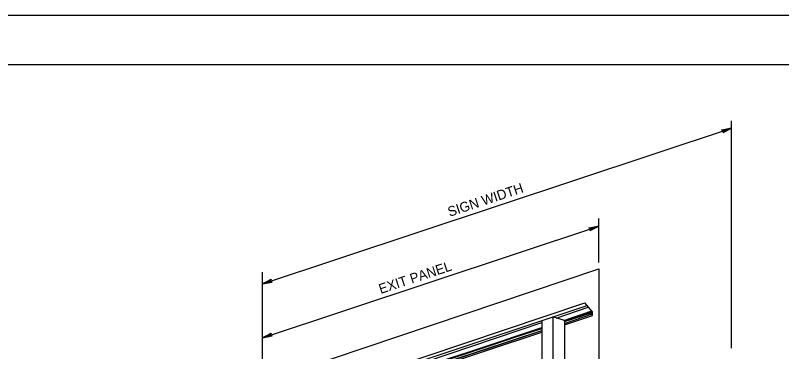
# Model space of a CAD drawing. Extents: x 650495 to 651400, y 297864 to 299646.
# Drawn here: x 650729.8 to 650964.3, y 299542.7 to 299645.6 of the extents above; entities that cross this region are included whole.
import ezdxf

# ---------------------------------------------------------------- set-up
doc = ezdxf.new("R2010")
doc.units = 0
for name, color, linetype in [('1', 7, 'Continuous'), ('2', 7, 'Continuous'), ('3', 7, 'Continuous'), ('PLT-BNDY', 7, 'Continuous')]:
    doc.layers.add(name, color=color, linetype=linetype)

# ---------------------------------------------------------------- blocks, each defined once
blk = doc.blocks.new('RARROW')
at = {"layer": '3'}
blk.add_lwpolyline([(-2.2695, 0.285), (-2.184875, 0.12075), (0, 0), (-2.2695, 0.285), (-2.38575, 0.384625), (0, 0), (-2.183125, -0.108), (-2.262875, -0.2705), (0, 0), (-2.38575, -0.379125), (-2.262875, -0.2705)], dxfattribs=at)

msp = doc.modelspace()

# ---------------------------------------------------------------- linework, layer by layer
at = {"layer": '1'}
msp.add_line((650535.31, 299630.63), (651321.31, 299630.63), dxfattribs=at)
at = {"layer": '2'}
for p, q in [((650948.9, 299543.77), (650948.9, 299613.37)), ((650805.4, 299563.47), (650948.9, 299611.07)), ((650908.3, 299569.97), (650908.3, 299583.47)), ((650805.4, 299546.97), (650908.3, 299581.07)), ((650908.3, 299581.07), (650908.3, 299581.07)), ((650805.4, 299533.47), (650908.3, 299568.07)), ((650805.4, 299535.47), (650805.4, 299567.07)), ((650908.3, 299568.07), (650908.3, 299528.47)), ((650809.3, 299525.87), (650904, 299557.67)), ((650906.4, 299554.87), (650904, 299557.67)), ((650904.7, 299556.77), (650832.8, 299532.87)), ((650895.3, 299552.97), (650905.1, 299556.37)), ((650897.6, 299552.27), (650906.2, 299555.17)), ((650897.8, 299552.17), (650906.4, 299554.87)), ((650897.8, 299551.97), (650906.4, 299554.67)), ((650906.4, 299553.77), (650906.4, 299554.97)), ((650890.9, 299552.27), (650890.9, 299482.47)), ((650894.3, 299553.37), (650894.3, 299483.87)), ((650897.8, 299552.27), (650894.3, 299553.37)), ((650897.8, 299551.37), (650906.4, 299554.27)), ((650897.8, 299550.97), (650906.4, 299553.77)), ((650897.8, 299552.27), (650897.8, 299482.67)), ((650832.8, 299532.07), (650890.9, 299551.67)), ((650834.4, 299531.27), (650890.9, 299550.07)), ((650834.7, 299531.17), (650890.9, 299549.87)), ((650833.9, 299531.57), (650890.9, 299549.77)), ((650837.1, 299531.57), (650890.9, 299549.17)), ((650837.1, 299531.37), (650891, 299549.17)), ((650837.1, 299530.97), (650890.9, 299548.67))]:
    msp.add_line(p, q, dxfattribs=at)
at = {"layer": 'PLT-BNDY'}
msp.add_lwpolyline([(650495.31, 299645.63), (651336.31, 299645.63), (651336.31, 299051.63), (650495.31, 299051.63)], close=True, dxfattribs=at)

# ---------------------------------------------------------------- block references
at = {"layer": '2'}
for p, xscale, yscale, rotation in [((650948.9, 299611.07), 1.2574347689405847, 1.3092961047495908, 18.89752500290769), ((650908.3, 299581.07), 1.2574347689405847, 1.3092961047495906, 18.36633733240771), ((650805.4, 299563.47), 1.2574347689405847, 1.3092961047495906, -161.6232987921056), ((650805.4, 299546.97), 1.2574347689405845, 1.3092961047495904, -161.19583579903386)]:
    msp.add_blockref('RARROW', p, dxfattribs=dict(at, xscale=xscale, yscale=yscale, rotation=rotation))

# ---------------------------------------------------------------- texts
for s, p in [('SIGN WIDTH', (650862.67, 299583.96)), ('EXIT PANEL', (650841.57, 299560.36))]:
    msp.add_text(s, height=3, rotation=18.3431, dxfattribs=at).set_placement(p)

doc.saveas('drawing.dxf')
